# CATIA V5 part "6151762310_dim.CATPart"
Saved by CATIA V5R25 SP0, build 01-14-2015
Part number: 6151762310_dim
Source: made
Property "PROI_CREATED_ON": "12/17/2008 9:21:37 AM"
Property "BLANK_DRAWING": "--"
Property "DRAWN_BY": "ALG"
Property "FINISH": "--"
Property "HEAT_TREATMENT": "ASSIGN"
Property "MATERIAL": "ASSIGN"
Property "PROJECT": "--"
Property "PROTOTYPE_NO": "--"
Property "RELATED_DRAWING": "--"
Property "COMPLETE_MATERIAL": "ASSIGN-ASSIGN"
Property "DESCRIPTION": "XPBM-6000"
Property "DRAWING_EXIST": "--"
Property "MANUFACTURER": "--"
Property "MANUFACTURER_2": "--"
Property "MANUFACTURER_REF": "--"
Property "TYPE_PART": "A"
Property "TODAY_DATE": "2023/06/07"
Property "PDMREV": "01.3"
Property "PDMRL": "Production"
Property "PROI_REVISION": "01"
Property "PROI_VERSION": "3"
Property "PROI_RELEASE": "Production"
Property "PTC_MODIFIED": false
Property "MFG_WP_MATERIAL": "ASSIGN"
Property "COMPANY_CODE": "---"
Property "DESCRIPTION_JP": "--"
Property "PQP_DOCUMENT": "--"
Property "SUPPLIER": "--"
Property "REFERENCE": "6151762310"
Property "PTC_WM_REVISION": "01"
Property "PTC_WM_ITERATION": "3"
Property "PTC_WM_VERSION": "01.3"
Property "PTC_WM_LIFECYCLE_STATE": "Production"
Property "PTC_WM_LIFECYCLE": "Design_Process"
Property "PTC_WM_LOCATION": "/Products/DRILLS TOOLS ASC/A1780 - XPB/9-01-Dimensional Drawings and 3D"
Property "PTC_WM_CREATED_BY": "Alain Le Goc (grealg) (grealg: CPD)"
Property "PTC_WM_CREATED_ON": "07-Jun-23 01:40:51 PM"
Property "PTC_WM_MODIFIED_BY": "Alain Le Goc (grealg) (grealg: CPD)"
Property "PTC_WM_MODIFIED_ON": "08-Jun-23 03:52:16 PM"
Property "PTC_WM_TEAM": "Default"
Property "PTC_ORGANIZATION_ID": "CPD"
Property "EXPORT_CONTROL": "NULL"
Property "PTC_WM_NAME": "6151762310_dim.prt"
Property "PTC_WM_NUMBER": "6151762310_DIM.PRT"
Property "PTC_COMMON_NAME": "6151762310_dim.prt"
Property "PTC_MASTER_MATERIAL": "ASSIGN"
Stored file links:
  d:\ptc\Echange\temp\6151762310_dim.CATPart

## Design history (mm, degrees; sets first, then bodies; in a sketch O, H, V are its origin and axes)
AxisSystem1 "CS0": origin (0, 0, 0), X (1, 0, 0), Y (0, 1, 0), Z (0, 0, 1)
Set1
  DatumSurface1 "Sheet.1"
  DatumSurface2 "Sheet.2"
  DatumSurface3 "Sheet.3"
  DatumSurface4 "Sheet.4"
  DatumSurface5 "Sheet.5"
  DatumSurface6 "Sheet.6"
  DatumSurface7 "Sheet.7"
  DatumSurface8 "Sheet.8"
  DatumSurface9 "Sheet.9"
  DatumSurface10 "Sheet.10"
  DatumSurface11 "Sheet.11"
  DatumSurface12 "Sheet.12"
  DatumSurface13 "Sheet.13"
  DatumSurface14 "Sheet.14"
  DatumSurface15 "Sheet.15"
  DatumSurface16 "Sheet.16"
  DatumSurface17 "Sheet.17"
  DatumSurface18 "Sheet.18"
  DatumSurface19 "Sheet.19"
  DatumSurface20 "Sheet.20"
  DatumSurface21 "Sheet.21"
  DatumSurface22 "Sheet.22"
  DatumSurface23 "Sheet.23"
  DatumSurface24 "Sheet.24"
  DatumSurface25 "Sheet.25"
  DatumSurface26 "Sheet.26"
  DatumSurface27 "Sheet.27"
  DatumSurface28 "Sheet.28"
  DatumSurface29 "Sheet.29"
  DatumSurface30 "Sheet.30"
  DatumSurface31 "Sheet.31"
  DatumSurface32 "Sheet.32"
  DatumSurface33 "Sheet.33"
  DatumSurface34 "Sheet.34"
  DatumSurface35 "Sheet.35"
  DatumSurface36 "Sheet.36"
  DatumSurface37 "Sheet.37"
  DatumSurface38 "Sheet.38"
  DatumSurface39 "Sheet.39"
  DatumSurface40 "Sheet.40"
  DatumSurface41 "Sheet.41"
  DatumSurface42 "Sheet.42"
  Plane1 "RIGHT": stored without definition
  Plane2 "TOP": stored without definition
  Plane3 "FRONT": stored without definition
Body1 "PartBody" (main body)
